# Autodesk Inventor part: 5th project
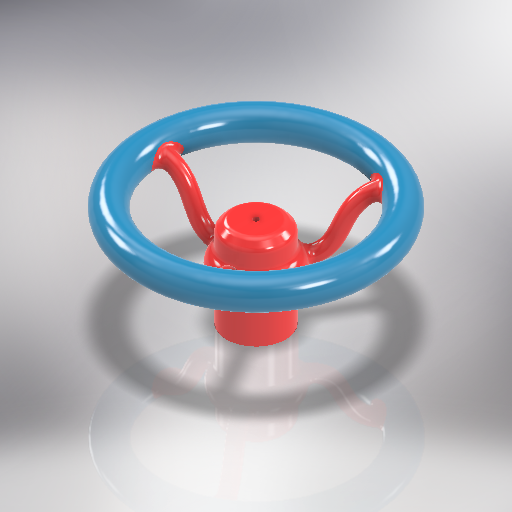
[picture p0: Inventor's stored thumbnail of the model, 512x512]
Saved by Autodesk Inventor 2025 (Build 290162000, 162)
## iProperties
Created: 2024-06
Part Number: 5th project
Material: Generic
Document SubType Name: Modeling
Designer: aryan
Density: 1 g/cm^3
Appearance: Light Red
Author: aryan
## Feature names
1. Revolution1
2. Sweep1
3. Circular Pattern1
4. Revolution2
5. Fillet1
6. Hole1
## Parameters: d0 = 25.4 mm, d1 = 76.2 mm, d2 = 6.35 mm, d3 = 6.35 mm, d4 = 25.4 mm, d5 = 44.45 mm, d6 = 90 deg, d7 = 12.7 mm, d8 = 0, d9 = 0, d11 = 360 deg, d13 = 25.4 mm, d14 = 90 deg, d15 = 6.35 mm, d16 = 4.9784 mm, d17 = 12.7 mm, d18 = 9.525 mm, d19 = 6.35 mm, d20 = 82 deg, d21 = 25.4 mm, d22 = 118 deg
